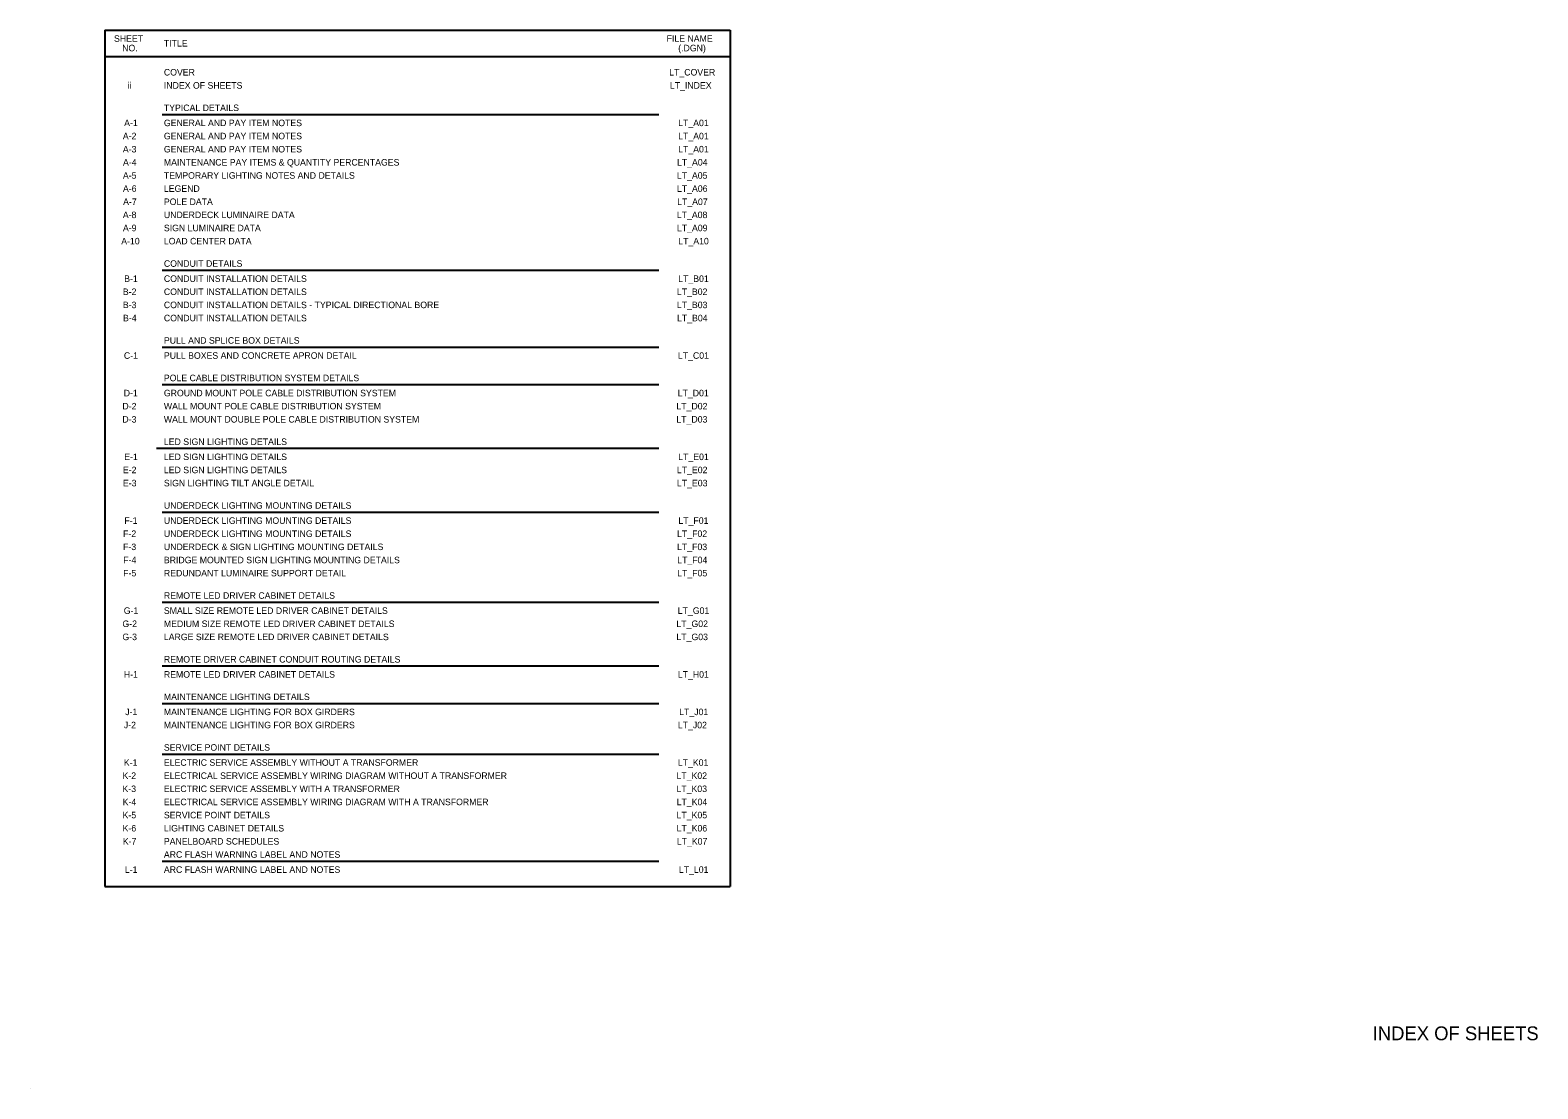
# Model space of a CAD drawing. Extents: x -39 to 1295, y -523 to -44.
# Drawn here: x -39 to 644, y -523 to -44 of the extents above; entities that cross this region are included whole.
import ezdxf

# ---------------------------------------------------------------- set-up
doc = ezdxf.new("R2010")
doc.units = 0
for name, color, linetype in [('AdhocPoint_dp', 7, 'Continuous'), ('SumBoxLines_dp', 7, 'Continuous'), ('SumBoxLinesMin_dp', 7, 'Continuous'), ('TextLabel', 7, 'Continuous'), ('TextMisc', 7, 'Continuous')]:
    doc.layers.add(name, color=color, linetype=linetype)

msp = doc.modelspace()

# ---------------------------------------------------------------- linework, layer by layer
at = {"layer": 'AdhocPoint_dp'}
msp.add_line((-39.15, -523.47), (-39.15, -523.47), dxfattribs=at)
at = {"layer": 'SumBoxLines_dp'}
for p, q in [((-5.35, -55.48), (18.08, -55.48)), ((-5.35, -55.48), (278.13, -55.48)), ((20.62, -55.48), (278.13, -55.48)), ((20.62, -81.74), (245.82, -81.74)), ((20.62, -81.74), (245.82, -81.74)), ((20.62, -152.34), (245.82, -152.34)), ((20.62, -152.34), (245.82, -152.34)), ((20.62, -187.2), (245.82, -187.2)), ((20.62, -187.2), (245.82, -187.2)), ((20.62, -204.2), (245.82, -204.2)), ((20.62, -204.2), (245.82, -204.2)), ((18.08, -233.11), (245.82, -233.11)), ((18.08, -233.11), (245.82, -233.11)), ((20.62, -262.01), (245.82, -262.01)), ((20.62, -262.01), (245.82, -262.01)), ((20.62, -302.83), (245.82, -302.83)), ((20.62, -302.83), (245.82, -302.83)), ((20.62, -331.74), (245.82, -331.74)), ((20.62, -331.74), (245.82, -331.74)), ((20.62, -348.74), (245.82, -348.74)), ((20.62, -348.74), (245.82, -348.74)), ((20.62, -371.69), (245.82, -371.69)), ((20.62, -371.69), (245.82, -371.69)), ((20.62, -420.22), (245.82, -420.22)), ((20.62, -420.22), (245.82, -420.22))]:
    msp.add_line(p, q, dxfattribs=at)
at = {"layer": 'SumBoxLinesMin_dp'}
for p, q in [((-5.35, -43.57), (278.13, -43.57)), ((-5.35, -43.57), (-5.35, -431.81)), ((278.13, -43.57), (278.13, -431.81)), ((-5.35, -431.81), (278.13, -431.81))]:
    msp.add_line(p, q, dxfattribs=at)

# ---------------------------------------------------------------- texts
at = {"layer": 'TextLabel'}
for s, height, p in [('SHEET', 2.956, (-1.15, -48.85)), ('FILE NAME', 2.956, (249.33, -48.85)), ('NO.', 2.956, (2.56, -53.15)), ('TITLE', 2.956, (21.46, -51)), ('(.DGN)', 2.956, (254.58, -53.15)), ('COVER', 2.956, (21.46, -64.13)), ('LT_COVER', 2.956, (250.5, -64.13)), ('ii', 2.956, (5.07, -70.09)), ('INDEX OF SHEETS', 2.9563, (21.46, -70.09)), ('LT_INDEX', 2.956, (250.8, -70.09)), ('TYPICAL DETAILS', 2.9563, (21.46, -80.25)), ('A-1', 2.956, (3.46, -87.09)), ('GENERAL AND PAY ITEM NOTES', 2.9563, (21.46, -87.09)), ('LT_A01', 2.956, (254.56, -87.09)), ('A-2', 2.956, (2.86, -93.04)), ('GENERAL AND PAY ITEM NOTES', 2.9563, (21.46, -93.04)), ('LT_A01', 2.956, (254.56, -93.04)), ('A-3', 2.956, (2.86, -99)), ('A-4', 2.956, (2.93, -104.95)), ('GENERAL AND PAY ITEM NOTES', 2.9563, (21.46, -99)), ('MAINTENANCE PAY ITEMS & QUANTITY PERCENTAGES', 2.9563, (21.46, -104.95)), ('LT_A04', 2.956, (254.03, -104.95)), ('LT_A01', 2.956, (254.56, -99)), ('A-5', 2.956, (2.89, -110.91)), ('TEMPORARY LIGHTING NOTES AND DETAILS', 2.9563, (21.46, -110.91)), ('LT_A05', 2.956, (253.99, -110.91)), ('A-6', 2.956, (2.91, -116.86)), ('LEGEND', 2.956, (21.46, -116.86)), ('LT_A06', 2.956, (254.01, -116.86)), ('A-7', 2.956, (2.99, -122.82)), ('POLE DATA', 2.956, (21.46, -122.82)), ('LT_A07', 2.956, (254.09, -122.82)), ('A-8', 2.956, (2.86, -128.77)), ('UNDERDECK LUMINAIRE DATA', 2.9563, (21.46, -128.77)), ('LT_A08', 2.956, (253.96, -128.77)), ('A-9', 2.956, (2.91, -134.72)), ('SIGN LUMINAIRE DATA', 2.9563, (21.46, -134.72)), ('LT_A09', 2.956, (254.01, -134.72)), ('A-10', 2.956, (2.13, -140.68)), ('LOAD CENTER DATA', 2.9563, (21.46, -140.68)), ('LT_A10', 2.956, (254.6, -140.68)), ('CONDUIT DETAILS', 2.9563, (21.46, -150.84)), ('B-1', 2.956, (3.48, -157.68)), ('CONDUIT INSTALLATION DETAILS', 2.9563, (21.46, -157.68)), ('LT_B01', 2.956, (254.58, -157.68)), ('B-2', 2.956, (2.88, -163.63)), ('CONDUIT INSTALLATION DETAILS', 2.9563, (21.46, -163.63)), ('LT_B02', 2.956, (253.98, -163.63)), ('B-3', 2.956, (2.87, -169.59)), ('CONDUIT INSTALLATION DETAILS - TYPICAL DIRECTIONAL BORE', 2.9563, (21.46, -169.59)), ('LT_B03', 2.956, (253.98, -169.59)), ('B-4', 2.956, (2.95, -175.54)), ('CONDUIT INSTALLATION DETAILS', 2.9563, (21.46, -175.54)), ('LT_B04', 2.956, (254.05, -175.54)), ('PULL AND SPLICE BOX DETAILS', 2.9563, (21.46, -185.7)), ('C-1', 2.956, (3.34, -192.54)), ('PULL BOXES AND CONCRETE APRON DETAIL', 2.9563, (21.46, -192.54)), ('LT_C01', 2.956, (254.44, -192.54)), ('POLE CABLE DISTRIBUTION SYSTEM DETAILS', 2.9563, (21.46, -202.7)), ('D-1', 2.956, (3.26, -209.54)), ('GROUND MOUNT POLE CABLE DISTRIBUTION SYSTEM', 2.9563, (21.46, -209.54)), ('LT_D01', 2.956, (254.36, -209.54)), ('D-2', 2.956, (2.66, -215.49)), ('D-3', 2.956, (2.65, -221.45)), ('WALL MOUNT POLE CABLE DISTRIBUTION SYSTEM', 2.9563, (21.46, -215.49)), ('WALL MOUNT DOUBLE POLE CABLE DISTRIBUTION SYSTEM', 2.9563, (21.46, -221.45)), ('LT_D02', 2.956, (253.76, -215.49)), ('LT_D03', 2.956, (253.75, -221.45)), ('LED SIGN LIGHTING DETAILS', 2.9563, (21.46, -231.61)), ('E-1', 2.956, (3.49, -238.45)), ('LED SIGN LIGHTING DETAILS', 2.9563, (21.46, -238.45)), ('LT_E01', 2.956, (254.59, -238.45)), ('E-2', 2.956, (2.89, -244.4)), ('LED SIGN LIGHTING DETAILS', 2.9563, (21.46, -244.4)), ('LT_E02', 2.956, (253.99, -244.4)), ('E-3', 2.956, (2.89, -250.36)), ('SIGN LIGHTING TILT ANGLE DETAIL', 2.9563, (21.46, -250.36)), ('LT_E03', 2.956, (253.99, -250.36)), ('UNDERDECK LIGHTING MOUNTING DETAILS', 2.9563, (21.46, -260.51)), ('F-1', 2.956, (3.57, -267.36)), ('UNDERDECK LIGHTING MOUNTING DETAILS', 2.9563, (21.46, -267.36)), ('LT_F01', 2.956, (254.67, -267.36)), ('F-2', 2.956, (2.98, -273.31)), ('UNDERDECK LIGHTING MOUNTING DETAILS', 2.9563, (21.46, -273.31)), ('LT_F02', 2.956, (254.08, -273.31)), ('F-3', 2.956, (2.97, -279.26)), ('UNDERDECK & SIGN LIGHTING MOUNTING DETAILS', 2.9563, (21.46, -279.26)), ('LT_F03', 2.956, (254.07, -279.26)), ('F-4', 2.956, (3.05, -285.22)), ('BRIDGE MOUNTED SIGN LIGHTING MOUNTING DETAILS', 2.9563, (21.46, -285.22)), ('LT_F04', 2.956, (254.15, -285.22)), ('F-5', 2.956, (3.01, -291.17)), ('REDUNDANT LUMINAIRE SUPPORT DETAIL', 2.9563, (21.46, -291.17)), ('LT_F05', 2.956, (254.11, -291.17)), ('REMOTE LED DRIVER CABINET DETAILS', 2.9563, (21.46, -301.33)), ('G-1', 2.956, (3.28, -308.17)), ('SMALL SIZE REMOTE LED DRIVER CABINET DETAILS', 2.9563, (21.46, -308.17)), ('LT_G01', 2.956, (254.38, -308.17)), ('G-2', 2.956, (2.68, -314.13)), ('MEDIUM SIZE REMOTE LED DRIVER CABINET DETAILS', 2.9563, (21.46, -314.13)), ('LT_G02', 2.956, (253.78, -314.13)), ('G-3', 2.956, (2.67, -320.08)), ('LARGE SIZE REMOTE LED DRIVER CABINET DETAILS', 2.9563, (21.46, -320.08)), ('LT_G03', 2.956, (253.77, -320.08)), ('REMOTE DRIVER CABINET CONDUIT ROUTING DETAILS', 2.9563, (21.46, -330.24)), ('H-1', 2.956, (3.3, -337.08)), ('REMOTE LED DRIVER CABINET DETAILS', 2.9563, (21.46, -337.08)), ('LT_H01', 2.956, (254.4, -337.08)), ('MAINTENANCE LIGHTING DETAILS', 2.9563, (21.46, -347.24)), ('J-1', 2.956, (3.91, -354.08)), ('MAINTENANCE LIGHTING FOR BOX GIRDERS', 2.9563, (21.46, -354.08)), ('LT_J01', 2.956, (255.01, -354.08)), ('J-2', 2.956, (3.31, -360.03)), ('MAINTENANCE LIGHTING FOR BOX GIRDERS', 2.9563, (21.46, -360.03)), ('LT_J02', 2.956, (254.41, -360.03)), ('SERVICE POINT DETAILS', 2.9563, (21.46, -370.19)), ('K-1', 2.956, (3.31, -377.03)), ('ELECTRIC SERVICE ASSEMBLY WITHOUT A TRANSFORMER', 2.9563, (21.46, -377.03)), ('LT_K01', 2.956, (254.41, -377.03)), ('K-2', 2.956, (2.71, -382.99)), ('ELECTRICAL SERVICE ASSEMBLY WIRING DIAGRAM WITHOUT A TRANSFORMER', 2.9563, (21.46, -382.99)), ('LT_K02', 2.956, (253.81, -382.99)), ('K-3', 2.956, (2.7, -388.94)), ('ELECTRIC SERVICE ASSEMBLY WITH A TRANSFORMER', 2.9563, (21.46, -388.94)), ('LT_K03', 2.956, (253.8, -388.94)), ('K-4', 2.956, (2.78, -394.9)), ('ELECTRICAL SERVICE ASSEMBLY WIRING DIAGRAM WITH A TRANSFORMER', 2.9563, (21.46, -394.9)), ('LT_K04', 2.956, (253.88, -394.9)), ('K-5', 2.956, (2.74, -400.85)), ('SERVICE POINT DETAILS', 2.9563, (21.46, -400.85)), ('LT_K05', 2.956, (253.84, -400.85)), ('K-6', 2.956, (2.76, -406.81)), ('K-7', 2.956, (2.84, -412.76)), ('LIGHTING CABINET DETAILS', 2.9563, (21.46, -406.81)), ('PANELBOARD SCHEDULES', 2.9563, (21.46, -412.76)), ('LT_K06', 2.956, (253.86, -406.81)), ('LT_K07', 2.956, (253.94, -412.76)), ('ARC FLASH WARNING LABEL AND NOTES', 2.9563, (21.46, -418.72)), ('L-1', 2.956, (3.78, -425.56)), ('ARC FLASH WARNING LABEL AND NOTES', 2.9563, (21.46, -425.56)), ('LT_L01', 2.956, (254.88, -425.56))]:
    msp.add_text(s, height=height, dxfattribs=at).set_placement(p)
at = {"layer": 'TextMisc'}
msp.add_text('       INDEX OF SHEETS         ', height=6.25, dxfattribs=at).set_placement((553.1, -501.43))

doc.saveas('drawing.dxf')
